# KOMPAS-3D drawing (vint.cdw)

Views: Вид 1
Referenced files: Чертеж1.cdw
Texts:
  Винт
  Текст на чертеже
  Размерные надписи
  Шероховатость
  Линия-выноска #1
  Линия-выноска #2
  Линия-выноска #3
  Отклонения формы и база
  Заголовок таблицы
  Ячейка таблицы
  Стрелка вида
  Обозначение изменения
  Фигурная скобка
  Номер узла
  Марка координационной оси
  VRCB
  Выносная надпись
  Обозначение узла
  Марка/позиционное обозначение с линией-выноской
  Марка/позиционное обозначение на линии
  Марка/позиционное обозначение без линии-выноски
  Symbol type A
  Кв.32Х4-7ZA/7h
  Сталь 4 ГОСТ 380-94
Dimensions and other numbers on the sheet: 61 00 T 04; 7; 243; 190; 4; 6; 2:1; 21; 5; 42; 2; 1:1; 1; 8; 61 00 T 04-; 0; 3; 9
